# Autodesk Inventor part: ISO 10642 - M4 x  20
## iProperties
Library Location: C:\Program Files\Autodesk\Inventor 6\content
Library: local
SubLibrary: ISO
Family: 3
Member: 15
Member Major Revision: 1
Member Minor Revision: 1
Comments: To add or edit properties for Autodesk Inventor files, use iProperties.
Created: 2003-02
Part Number: ISO 10642 - M4 x  20
Vendor: Autodesk Inc.
Document SubType Name: Modeling
Designer: hofer_a
Description: Innensechskantschraube mit Senkkopf
Standard: ISO 10642 M4 x  20
Alert: To add or edit properties for Autodesk Inventor files, use iProperties.
Control State: 0
Master: False
Checked Out: False
Shininess: 64.0
Length Units: 11269
Angle Units: 11279
Time Units: 11290
Mass Units: 11283
Length Display Precision: 3
Angle Display Precision: 2
Compacted: True
EGR: 1
Density: 0.0
Volumn: 0.0
Area: 0.0
PropertySet Name: Model Information
Author: hofer_a
Revision Number: 1
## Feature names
1. Körper [Revolution]
2. Loch [Extrusion]
3. Fase1 [Chamfer]
